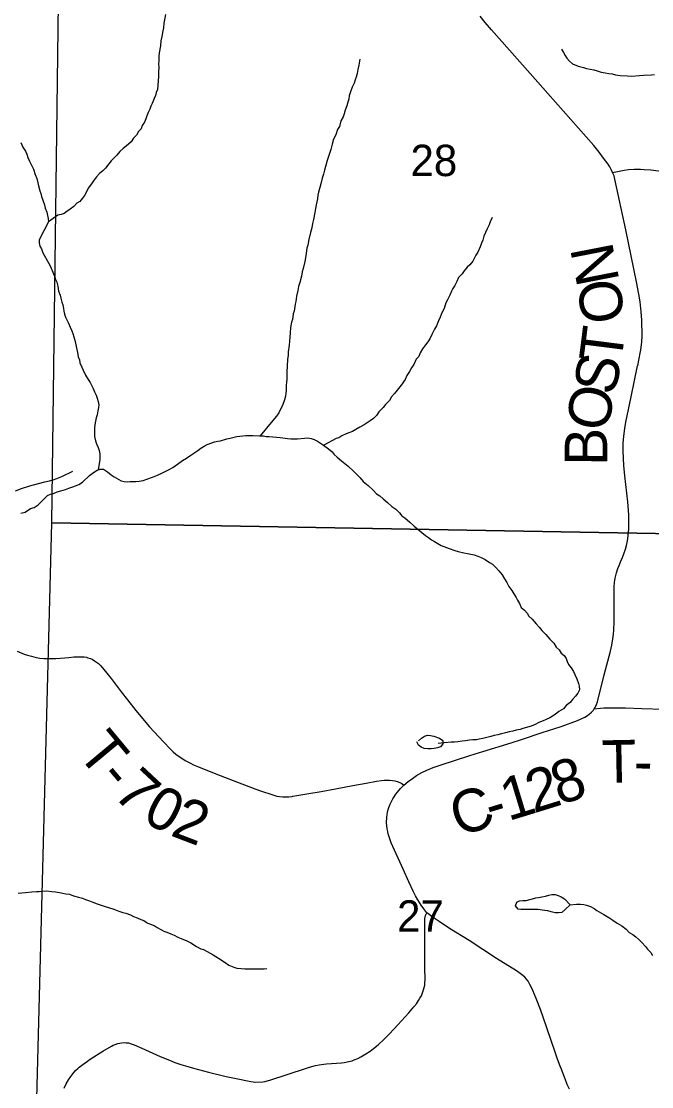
# Model space of a CAD drawing. Extents: x 0 to 34, y 0 to 22.
# Drawn here: x 27.832 to 28.673, y 16.803 to 18.224 of the extents above; entities that cross this region are included whole.
import ezdxf

# ---------------------------------------------------------------- set-up
doc = ezdxf.new("R2010")
doc.units = 0
for name, color, linetype in [('GM_X_Corporation', 7, 'Continuous'), ('GM_X_County_Road', 7, 'Continuous'), ('GM_X_County_Road_Text', 7, 'Continuous'), ('GM_X_Minor_River', 7, 'Continuous'), ('GM_X_Section_Text', 7, 'Continuous'), ('GM_X_Township_Road', 7, 'Continuous'), ('GM_X_Township_Road_Text', 7, 'Continuous')]:
    doc.layers.add(name, color=color, linetype=linetype)

msp = doc.modelspace()

# ---------------------------------------------------------------- linework, layer by layer
at = {"layer": 'GM_X_Corporation'}
for points in [[(28.8973, 18.5532), (28.8799, 17.5369), (27.873, 17.5549), (27.8861, 18.5601)], [(27.873, 17.5549), (28.8799, 17.5369), (28.863, 16.5324), (27.8467, 16.5483)]]:
    msp.add_lwpolyline(points, close=True, dxfattribs=at)
at = {"layer": 'GM_X_County_Road'}
for points in [[(28.6212, 18.0221), (28.6193, 18.0261), (28.6174, 18.0296), (28.6151, 18.0333), (28.6091, 18.0412), (28.6035, 18.0489), (28.596, 18.0578), (28.535, 18.1273), (28.5216, 18.1425), (28.4597, 18.2123), (28.4513, 18.222), (28.4445, 18.2303)], [(28.5637, 16.7997), (28.5607, 16.8061), (28.5582, 16.812), (28.5524, 16.8271), (28.5511, 16.8305), (28.5489, 16.8364), (28.5473, 16.8413), (28.5446, 16.8493), (28.5285, 16.8956), (28.5248, 16.9058), (28.5192, 16.9207), (28.5148, 16.9314), (28.5126, 16.9361), (28.511, 16.9392), (28.5085, 16.9436), (28.5062, 16.9466), (28.5039, 16.9492), (28.5013, 16.9515), (28.4979, 16.9542), (28.4928, 16.9577), (28.4662, 16.9742), (28.4299, 16.9978), (28.4038, 17.0138), (28.3897, 17.0231), (28.3806, 17.0295), (28.3763, 17.0328), (28.3735, 17.035), (28.3693, 17.0403), (28.366, 17.0449), (28.3612, 17.052), (28.3582, 17.0576), (28.355, 17.0639), (28.3495, 17.076), (28.3417, 17.0931), (28.326, 17.1282), (28.3235, 17.135), (28.322, 17.14), (28.3212, 17.1434), (28.3206, 17.1467), (28.32, 17.151), (28.3197, 17.1548), (28.3199, 17.1625), (28.3203, 17.1659), (28.3208, 17.1687), (28.3218, 17.1725), (28.3227, 17.1755), (28.3244, 17.1798), (28.3265, 17.184), (28.328, 17.1868), (28.3297, 17.1895), (28.3322, 17.1932), (28.3343, 17.1959), (28.3383, 17.2008), (28.3425, 17.2052), (28.3486, 17.2102), (28.3542, 17.2141), (28.3596, 17.2178), (28.3665, 17.2218), (28.3734, 17.2251), (28.3819, 17.2285), (28.3911, 17.2316), (28.4308, 17.2445), (28.4479, 17.2498), (28.4859, 17.2615), (28.4995, 17.2659), (28.5272, 17.2751), (28.5524, 17.2835), (28.5743, 17.2912), (28.5794, 17.2935), (28.5841, 17.2959), (28.5875, 17.2979), (28.5901, 17.2998), (28.5931, 17.3023), (28.5956, 17.3051), (28.5968, 17.3067), (28.598, 17.3087), (28.5999, 17.3128), (28.6012, 17.3163), (28.61, 17.3524), (28.6183, 17.3837), (28.6201, 17.3918), (28.6214, 17.4001), (28.6222, 17.4063), (28.6227, 17.4117), (28.6232, 17.4235), (28.6235, 17.4404), (28.6233, 17.4655), (28.6234, 17.4693), (28.6239, 17.4752), (28.6248, 17.4811), (28.6256, 17.4847), (28.6265, 17.4884), (28.6283, 17.4941), (28.6298, 17.4981), (28.6324, 17.5039), (28.6343, 17.5085), (28.6361, 17.5135), (28.6383, 17.5196), (28.6397, 17.5246), (28.6406, 17.5288), (28.6414, 17.5336), (28.6421, 17.5386), (28.6428, 17.5466), (28.643, 17.5529), (28.6428, 17.5654), (28.6414, 17.5827), (28.6376, 17.6176), (28.6362, 17.6314), (28.6356, 17.6407), (28.6353, 17.6509), (28.6355, 17.6609), (28.6358, 17.6658), (28.6366, 17.6739), (28.6375, 17.6807), (28.6389, 17.6891), (28.6459, 17.7231), (28.6546, 17.764), (28.6547, 17.7646), (28.6566, 17.774), (28.658, 17.7813), (28.6587, 17.7855), (28.66, 17.7959), (28.6606, 17.8042), (28.6603, 17.8249), (28.6595, 17.8362), (28.6579, 17.8494), (28.6563, 17.8599), (28.653, 17.8761), (28.6387, 17.9456), (28.6244, 18.0129), (28.6231, 18.0176), (28.6212, 18.0221)], [(28.6212, 18.0221), (28.6368, 18.0251), (28.6424, 18.0258), (28.65, 18.0263), (28.6586, 18.0264), (28.6633, 18.0262), (28.672, 18.0255), (28.6963, 18.0226)]]:
    msp.add_lwpolyline(points, dxfattribs=at)
at = {"layer": 'GM_X_Minor_River'}
for points in [[(28.0247, 18.2327), (28.0227, 18.2213), (28.022, 18.2148), (28.021, 18.211), (28.02, 18.2034), (28.0185, 18.1977), (28.0179, 18.1909), (28.0162, 18.1814), (28.0159, 18.1768), (28.016, 18.1707), (28.0153, 18.1666), (28.0157, 18.1628), (28.0155, 18.1552), (28.0152, 18.1502), (28.0147, 18.1385), (28.014, 18.1328), (28.0122, 18.1286), (28.0115, 18.1248), (28.0097, 18.1206), (28.0071, 18.1141), (28.0053, 18.1103), (28.0039, 18.1064), (28.0017, 18.1022), (27.9999, 18.0976), (27.9984, 18.0934), (27.9966, 18.0892), (27.9937, 18.0846), (27.9922, 18.0804), (27.9889, 18.0766), (27.9859, 18.0716), (27.9822, 18.0677), (27.9789, 18.0631), (27.9722, 18.057), (27.9681, 18.0538), (27.9636, 18.05), (27.9599, 18.045), (27.9521, 18.0376), (27.9491, 18.0334), (27.9447, 18.0276), (27.941, 18.0242), (27.9365, 18.0207), (27.9328, 18.0161), (27.9287, 18.0107), (27.9258, 18.0068), (27.9217, 18.0011), (27.9199, 17.9969), (27.9166, 17.9915), (27.914, 17.9877), (27.9103, 17.9834), (27.9065, 17.9811), (27.9025, 17.9768), (27.8976, 17.973), (27.8931, 17.9702), (27.8894, 17.9675), (27.8856, 17.9659), (27.8811, 17.9651), (27.8688, 17.9561), (27.8563, 17.9324), (27.8564, 17.9282), (27.8572, 17.9237), (27.8592, 17.92), (27.8612, 17.9151), (27.8686, 17.9015), (27.8713, 17.8967), (27.8753, 17.8869), (27.8772, 17.8831), (27.878, 17.8793), (27.8796, 17.8756), (27.8809, 17.8703), (27.8821, 17.8639), (27.8841, 17.8586)], [(28.553, 18.1864), (28.5557, 18.1819), (28.5577, 18.1781), (28.56, 18.1743), (28.5635, 18.1706), (28.5677, 18.1669), (28.5753, 18.164), (28.5826, 18.1619), (28.5864, 18.1608), (28.5963, 18.1587), (28.6008, 18.1576), (28.6061, 18.1558), (28.6115, 18.1548), (28.616, 18.1541), (28.6206, 18.1534), (28.6251, 18.1524), (28.6312, 18.1513), (28.641, 18.1508), (28.6467, 18.1505), (28.6569, 18.1514), (28.6626, 18.1519), (28.6732, 18.1521), (28.6773, 18.1525)], [(28.2838, 18.1732), (28.2825, 18.1649), (28.2814, 18.1595), (28.2804, 18.1538), (28.279, 18.1492), (28.2779, 18.1454), (28.2765, 18.1412), (28.2739, 18.1359), (28.2717, 18.1294), (28.2699, 18.1244), (28.2693, 18.1199), (28.2678, 18.1157), (28.2668, 18.1111), (28.2646, 18.105), (28.2632, 18.1004), (28.2617, 18.0962), (28.2588, 18.0909), (28.2567, 18.0832), (28.2541, 18.0794), (28.2519, 18.0722), (28.249, 18.0664), (28.2472, 18.0599), (28.2455, 18.0527), (28.2404, 18.0382), (28.2383, 18.0302), (28.2369, 18.0252), (28.2354, 18.0199), (28.2336, 18.0146), (28.2322, 18.0085), (28.2305, 18.002), (28.2287, 17.9959), (28.228, 17.9917), (28.2273, 17.9868), (28.2259, 17.9788), (28.2249, 17.9738), (28.2238, 17.9685), (28.2221, 17.9594), (28.2207, 17.954), (28.22, 17.9483), (28.2183, 17.9419), (28.2161, 17.9327), (28.2148, 17.9251), (28.2133, 17.9209), (28.212, 17.911), (28.2106, 17.9034), (28.2085, 17.8939), (28.2071, 17.8897), (28.206, 17.8836), (28.2039, 17.8752), (28.2021, 17.8699), (28.2011, 17.8646), (28.1993, 17.857), (28.1987, 17.8501), (28.1976, 17.8463), (28.1962, 17.8372), (28.1952, 17.8334), (28.1942, 17.8262), (28.1927, 17.8223), (28.1917, 17.8155), (28.1911, 17.8083), (28.1904, 17.8026), (28.1895, 17.7916), (28.1885, 17.7828), (28.1882, 17.7783), (28.1875, 17.7726), (28.1869, 17.7638), (28.1867, 17.7563), (28.1864, 17.7513), (28.1865, 17.7464), (28.1862, 17.7426), (28.1859, 17.738), (28.1856, 17.7324), (28.1853, 17.7274), (28.1846, 17.7236), (28.1835, 17.719), (28.1807, 17.7114), (28.1781, 17.7064), (28.1759, 17.7015), (28.173, 17.6969), (28.1659, 17.6888), (28.1511, 17.6707)], [(27.8317, 18.062), (27.8345, 18.0556)], [(27.8345, 18.0556), (27.838, 18.0504), (27.8396, 18.0466), (27.8412, 18.0421), (27.8435, 18.0372), (27.8455, 18.0327), (27.8486, 18.0263), (27.851, 18.0192), (27.853, 18.0139), (27.8542, 18.0082), (27.8554, 18.0041), (27.8571, 17.9977), (27.8586, 17.9939), (27.8591, 17.9901), (27.8631, 17.9788), (27.8643, 17.9746), (27.8663, 17.969), (27.8675, 17.9645), (27.8683, 17.9607), (27.8688, 17.9561)], [(28.4604, 17.9621), (28.4579, 17.956), (28.4565, 17.9522), (28.4539, 17.9468), (28.4495, 17.9369), (28.4481, 17.9319), (28.4463, 17.9277), (28.4445, 17.9228), (28.4412, 17.9159), (28.4386, 17.9117), (28.4346, 17.9036), (28.4309, 17.899), (28.4272, 17.8959), (28.4231, 17.8909), (28.4205, 17.8871), (28.4157, 17.882), (28.4135, 17.8767), (28.4106, 17.8713), (28.408, 17.8675), (28.4062, 17.8637), (28.404, 17.8583), (28.4011, 17.8522), (28.3989, 17.848), (28.3963, 17.8407), (28.3934, 17.835), (28.3912, 17.8293), (28.3891, 17.8243), (28.3862, 17.8174), (28.3836, 17.8132), (28.3803, 17.8067), (28.3774, 17.8002), (28.3748, 17.7964), (28.3718, 17.7922), (28.3678, 17.7868), (28.3645, 17.7814), (28.3627, 17.7768), (28.3593, 17.773), (28.356, 17.7661), (28.3531, 17.7615), (28.3501, 17.7565), (28.3468, 17.7515), (28.3443, 17.7462), (28.3391, 17.7385), (28.3354, 17.7342), (28.3302, 17.7273), (28.3261, 17.7227), (28.3236, 17.7181), (28.3184, 17.7127), (28.315, 17.7085), (28.3095, 17.7027), (28.3061, 17.6981), (28.3024, 17.6939), (28.2976, 17.6907), (28.2938, 17.6884), (28.2897, 17.6857), (28.2841, 17.6825), (28.2788, 17.6794), (28.274, 17.6767), (28.2695, 17.6747), (28.2657, 17.6735), (28.2601, 17.6711), (28.2559, 17.6684), (28.2522, 17.6672), (28.236, 17.6583)], [(27.8841, 17.8586), (27.8849, 17.8544), (27.8865, 17.8491), (27.8877, 17.8454), (27.8886, 17.8408), (27.889, 17.8371), (27.8898, 17.8329), (27.8914, 17.8291), (27.8953, 17.8209), (27.8977, 17.8156), (27.8997, 17.8111), (27.9013, 17.8073), (27.9025, 17.8028), (27.9041, 17.7968), (27.9057, 17.79), (27.9065, 17.7862), (27.9074, 17.782), (27.9082, 17.7764), (27.9098, 17.7722), (27.9106, 17.7684), (27.913, 17.7624), (27.915, 17.7583), (27.9181, 17.7519), (27.9216, 17.7459), (27.924, 17.7421), (27.9259, 17.7384), (27.9283, 17.7342), (27.9302, 17.7297), (27.9322, 17.7252), (27.9334, 17.7211), (27.935, 17.7165), (27.9358, 17.7124), (27.9355, 17.7086), (27.9344, 17.7044), (27.9334, 17.6991), (27.9323, 17.6949), (27.9313, 17.6903), (27.9306, 17.6854), (27.9299, 17.6816), (27.9301, 17.6698), (27.9314, 17.6642), (27.9326, 17.6604), (27.9349, 17.6555), (27.9361, 17.6513), (27.937, 17.6468), (27.9371, 17.6392), (27.9347, 17.6255)], [(27.9472, 17.6231), (27.9522, 17.619), (27.9564, 17.6161), (27.9656, 17.6109), (27.9698, 17.6099), (27.9739, 17.6095), (27.9777, 17.61), (27.9853, 17.6101), (27.9894, 17.6106), (27.9951, 17.6114), (28, 17.613), (28.0075, 17.6158), (28.0139, 17.6186), (28.0207, 17.6214), (28.0297, 17.6261), (28.0345, 17.6288), (28.0409, 17.6331), (28.0476, 17.6378), (28.0528, 17.6413), (28.0585, 17.6452), (28.0678, 17.6514), (28.0719, 17.6545), (28.0764, 17.6569), (28.0805, 17.6592), (28.0865, 17.6616), (28.0903, 17.6628), (28.0945, 17.6636), (28.0982, 17.6644), (28.1065, 17.6669), (28.111, 17.6677), (28.1163, 17.6693), (28.1201, 17.6698), (28.128, 17.671), (28.1318, 17.6715), (28.1371, 17.6712), (28.1412, 17.6713), (28.15, 17.6707), (28.1553, 17.6708), (28.159, 17.6701), (28.1632, 17.6698), (28.1727, 17.6692), (28.1776, 17.6685), (28.1814, 17.6682), (28.1875, 17.6675), (28.192, 17.6669), (28.2007, 17.667), (28.2102, 17.6679), (28.2147, 17.668), (28.2189, 17.6673), (28.2231, 17.6659), (28.2273, 17.6637), (28.2357, 17.6585), (28.2422, 17.6537), (28.2472, 17.6496), (28.2499, 17.6459), (28.2537, 17.6426), (28.2595, 17.6377), (28.2641, 17.634), (28.2683, 17.6303), (28.2753, 17.624), (28.2845, 17.615), (28.2884, 17.6098), (28.2949, 17.6046), (28.3018, 17.5983), (28.3061, 17.5934), (28.3106, 17.5909), (28.3149, 17.5871), (28.321, 17.5819), (28.3268, 17.5767), (28.3318, 17.573), (28.3371, 17.5682), (28.3399, 17.5641), (28.3441, 17.5615), (28.3506, 17.5559), (28.3564, 17.5503), (28.3667, 17.5422), (28.3717, 17.5381), (28.3756, 17.5355), (28.3794, 17.5322), (28.3836, 17.53), (28.3882, 17.5274), (28.3924, 17.5248), (28.3962, 17.5234), (28.4031, 17.5208), (28.4107, 17.5179), (28.4152, 17.5165), (28.4228, 17.5151), (28.4278, 17.5141), (28.4319, 17.513), (28.4365, 17.5123), (28.4414, 17.5105), (28.446, 17.5087), (28.451, 17.5058), (28.4571, 17.5021), (28.4609, 17.4999), (28.4656, 17.4954), (28.4694, 17.4909), (28.4737, 17.4857), (28.4768, 17.4804), (28.4803, 17.4752), (28.4826, 17.4699)], [(27.8316, 17.5676), (27.8373, 17.5692), (27.8448, 17.5739), (27.8497, 17.5755), (27.8549, 17.579), (27.859, 17.5829), (27.8635, 17.5875), (27.8675, 17.5914), (27.8713, 17.5929), (27.8751, 17.5942), (27.8803, 17.5961), (27.8852, 17.5974), (27.8912, 17.5994), (27.8958, 17.601), (27.901, 17.603), (27.9048, 17.6042), (27.9093, 17.6061), (27.9138, 17.6092), (27.9235, 17.6178), (27.9287, 17.622), (27.9336, 17.6251), (27.9377, 17.6263), (27.9422, 17.6264), (27.9472, 17.6231)], [(28.4826, 17.4699), (28.4869, 17.4647), (28.4896, 17.4602), (28.4927, 17.4553), (28.4943, 17.4516), (28.497, 17.4474), (28.4994, 17.4422), (28.5036, 17.4385), (28.5071, 17.4343), (28.5094, 17.4306), (28.5137, 17.4265), (28.5191, 17.4202), (28.5233, 17.4157), (28.5268, 17.4112), (28.5322, 17.406), (28.5376, 17.3996), (28.543, 17.3944), (28.5461, 17.3892), (28.5499, 17.3854), (28.5527, 17.3809), (28.5565, 17.378), (28.5592, 17.3739), (28.5608, 17.3701), (28.5624, 17.3659), (28.5659, 17.3615), (28.569, 17.3566), (28.5706, 17.3528), (28.5733, 17.3468), (28.5757, 17.3408), (28.5765, 17.337), (28.577, 17.3321), (28.5748, 17.3279), (28.5718, 17.3237), (28.5677, 17.3194), (28.5644, 17.3152), (28.5592, 17.3113), (28.5555, 17.3067), (28.5495, 17.3032), (28.5446, 17.2993), (28.5375, 17.295), (28.5326, 17.2926), (28.5285, 17.291), (28.5229, 17.2887), (28.518, 17.2859), (28.5124, 17.2839), (28.5014, 17.2807), (28.4977, 17.2795), (28.4924, 17.2786), (28.4883, 17.2771), (28.483, 17.2762), (28.4781, 17.275), (28.4732, 17.2734), (28.4683, 17.2721), (28.4634, 17.2713), (28.4589, 17.2701), (28.4532, 17.2688), (28.4483, 17.2672), (28.4434, 17.2664), (28.4397, 17.2656), (28.4347, 17.2655), (28.4302, 17.265), (28.4249, 17.2642), (28.4204, 17.2637), (28.4147, 17.2629), (28.4102, 17.2624), (28.4057, 17.2623), (28.3966, 17.2614), (28.3887, 17.2605)], [(28.3621, 17.2642), (28.3662, 17.2677), (28.3703, 17.2704), (28.3741, 17.2716), (28.3783, 17.2713), (28.3828, 17.2706), (28.3904, 17.2677), (28.3946, 17.2648), (28.3947, 17.2602), (28.3914, 17.2564), (28.3876, 17.2548), (28.3831, 17.254), (28.3793, 17.2535), (28.3748, 17.2534), (28.3699, 17.2541), (28.366, 17.2556), (28.3622, 17.2585), (28.3602, 17.2627)], [(27.8283, 17.0611), (27.8378, 17.062), (27.8465, 17.0629), (27.8525, 17.0634), (27.8563, 17.0634), (27.8608, 17.0639), (27.8665, 17.064), (27.8733, 17.0634)], [(27.8733, 17.0634), (27.8779, 17.0627), (27.8832, 17.062), (27.8877, 17.0613), (27.8919, 17.0603), (27.8968, 17.0596), (27.9022, 17.0574), (27.9086, 17.0556), (27.914, 17.0546), (27.9181, 17.0528), (27.9235, 17.051), (27.928, 17.0492), (27.9334, 17.047), (27.9391, 17.0452), (27.9444, 17.0434), (27.9486, 17.0419), (27.9558, 17.0398), (27.9623, 17.0373), (27.968, 17.0355), (27.9718, 17.0344), (27.9779, 17.0322), (27.9821, 17.03), (27.9871, 17.0282), (27.9916, 17.026), (27.9958, 17.0246), (28.0004, 17.0216), (28.0058, 17.0191), (28.0096, 17.018), (28.0134, 17.0154), (28.0187, 17.0125), (28.0226, 17.0103), (28.0267, 17.0092), (28.0317, 17.007), (28.0363, 17.0052), (28.0412, 17.0026), (28.0458, 17.0008), (28.0531, 16.9975), (28.0584, 16.995), (28.0661, 16.9898), (28.0718, 16.9869), (28.0756, 16.9858), (28.0802, 16.9832), (28.0882, 16.9788), (28.0955, 16.9744), (28.1043, 16.9685), (28.1092, 16.9652), (28.1161, 16.9623), (28.1199, 16.9612), (28.1256, 16.9605), (28.1305, 16.9602), (28.1343, 16.9603), (28.1381, 16.96), (28.1562, 16.9603), (28.16, 16.9608)], [(28.5647, 17.0454), (28.5579, 17.0394), (28.5534, 17.0352), (28.5492, 17.0347), (28.5447, 17.035), (28.5394, 17.0361), (28.5348, 17.0375), (28.531, 17.0382), (28.5272, 17.0385), (28.5219, 17.0392), (28.5177, 17.0391), (28.5128, 17.0394), (28.5037, 17.0392), (28.4988, 17.0395), (28.495, 17.0398), (28.4916, 17.044), (28.4934, 17.0489), (28.4971, 17.0509), (28.5016, 17.0513), (28.5058, 17.0514), (28.5107, 17.0526), (28.5145, 17.0535), (28.5186, 17.0547), (28.5224, 17.0551), (28.5269, 17.056), (28.5318, 17.0572), (28.5363, 17.0584), (28.5401, 17.0592), (28.5446, 17.0593), (28.5484, 17.0582), (28.5526, 17.056), (28.5572, 17.0535), (28.5647, 17.0454)], [(28.5647, 17.0454), (28.5732, 17.0465), (28.5785, 17.0466), (28.5827, 17.0459), (28.5865, 17.0453), (28.5918, 17.0431), (28.5964, 17.0405), (28.6003, 17.0379), (28.6094, 17.0328), (28.6163, 17.0287), (28.6217, 17.025), (28.6274, 17.0213), (28.6335, 17.0177), (28.6393, 17.0132), (28.6431, 17.0087), (28.6481, 17.0058), (28.652, 17.0028), (28.6562, 16.9991), (28.66, 16.9954), (28.665, 16.9902), (28.6677, 16.9864), (28.672, 16.9819), (28.6743, 16.9782)]]:
    msp.add_lwpolyline(points, dxfattribs=at)
at = {"layer": 'GM_X_Township_Road'}
for points in [[(27.8244, 17.5976), (27.8324, 17.6007), (27.8436, 17.6044), (27.8551, 17.6075), (27.8639, 17.6096), (27.8698, 17.6108), (27.8747, 17.6121), (27.8799, 17.614), (27.8863, 17.6167), (27.9013, 17.6236)], [(27.827, 17.3837), (27.8362, 17.3799), (27.8405, 17.3785), (27.8458, 17.3769), (27.8524, 17.3754), (27.8572, 17.3745), (27.8624, 17.3739), (27.8671, 17.3738), (27.8784, 17.374), (27.8846, 17.3744), (27.8906, 17.3749), (27.8959, 17.3754), (27.9026, 17.3761), (27.9074, 17.3763), (27.9128, 17.3763), (27.916, 17.3761), (27.9193, 17.3756), (27.9213, 17.3749), (27.9247, 17.3738), (27.9267, 17.3729), (27.9302, 17.3708), (27.9327, 17.3691), (27.9352, 17.3671), (27.9386, 17.3641), (27.9466, 17.3545), (27.9524, 17.3471), (27.9658, 17.3296), (27.974, 17.3187), (27.9851, 17.3047), (28.0034, 17.283), (28.0094, 17.2763), (28.0219, 17.2629), (28.0313, 17.253), (28.035, 17.2496), (28.0387, 17.2466), (28.0416, 17.2443), (28.0463, 17.241), (28.0508, 17.238), (28.0571, 17.2347), (28.0623, 17.2323), (28.0686, 17.2296), (28.0743, 17.2272), (28.0977, 17.2181), (28.1206, 17.2091), (28.1451, 17.1998), (28.1514, 17.1974), (28.1678, 17.1921), (28.1731, 17.1906), (28.1768, 17.19), (28.1814, 17.1896), (28.1857, 17.1895), (28.1892, 17.1897), (28.1935, 17.1902), (28.1945, 17.1904)], [(28.5968, 17.3067), (28.6049, 17.3076), (28.6094, 17.308), (28.6147, 17.3083), (28.6179, 17.3083), (28.6382, 17.3082), (28.6601, 17.3074), (28.689, 17.3065)], [(28.1945, 17.1904), (28.2134, 17.1935), (28.2324, 17.1965), (28.2517, 17.2002), (28.2746, 17.2046), (28.2923, 17.2079), (28.3063, 17.2104), (28.3131, 17.2115), (28.3163, 17.2117), (28.3196, 17.2118), (28.3237, 17.2117), (28.3275, 17.2114), (28.3305, 17.2109), (28.3339, 17.21), (28.3373, 17.2086), (28.3398, 17.2071), (28.3425, 17.2052)], [(27.8894, 16.8012), (27.892, 16.8068), (27.8951, 16.812), (27.8983, 16.8167), (27.9009, 16.82), (27.9048, 16.8245), (27.9076, 16.8271), (27.9097, 16.8291), (27.9256, 16.8405), (27.9409, 16.8502), (27.9528, 16.8572), (27.9547, 16.8583), (27.9574, 16.8595), (27.9612, 16.8608), (27.9637, 16.8613), (27.9662, 16.8617), (27.9704, 16.8619), (27.9724, 16.8617), (27.9752, 16.8614), (27.9791, 16.8604), (27.9828, 16.8589), (27.993, 16.8544), (28.003, 16.8498), (28.0178, 16.8432), (28.03, 16.8382), (28.0371, 16.8355), (28.0454, 16.8327), (28.0516, 16.8307), (28.062, 16.8277), (28.082, 16.8225), (28.1055, 16.8168), (28.1188, 16.8141), (28.1386, 16.8099), (28.1448, 16.8093), (28.1544, 16.8096), (28.1571, 16.81), (28.1622, 16.8112), (28.1638, 16.8116), (28.2114, 16.8271), (28.217, 16.8291), (28.2247, 16.8312), (28.2297, 16.8322), (28.2361, 16.8332), (28.2394, 16.8335), (28.2595, 16.8349), (28.2632, 16.8353), (28.2694, 16.8365), (28.2736, 16.8376), (28.2766, 16.8387), (28.2811, 16.8405), (28.2855, 16.8427), (28.2921, 16.8467), (28.2977, 16.8506), (28.3022, 16.8539), (28.3086, 16.859), (28.316, 16.8661), (28.3234, 16.8737), (28.3346, 16.8855), (28.3493, 16.9017), (28.3562, 16.9095), (28.3594, 16.9137), (28.3624, 16.918), (28.3642, 16.9211), (28.3661, 16.9244), (28.3678, 16.9282), (28.369, 16.9323), (28.3698, 16.9352), (28.3705, 16.9386), (28.3709, 16.9419), (28.371, 16.9451), (28.3709, 16.9625), (28.3706, 16.9759), (28.3709, 17.0275), (28.3718, 17.0311), (28.3735, 17.035)]]:
    msp.add_lwpolyline(points, dxfattribs=at)

# ---------------------------------------------------------------- texts
at = {"layer": 'GM_X_County_Road_Text'}
for s, rotation, p in [('N', 101.0152, (28.6305, 17.8777)), ('O', 97.7259, (28.6378, 17.8247)), ('T', 82.8184, (28.6326, 17.7664)), ('S', 77.4903, (28.6233, 17.7233)), ('O', 79.1637, (28.614, 17.6746)), ('B', 89.5355, (28.6139, 17.6307)), ('8', 18.3239, (28.5503, 17.1781)), ('1', 16.8925, (28.4819, 17.157)), ('2', 17.2927, (28.5158, 17.1673)), ('C', 18.0067, (28.4155, 17.1359)), ('-', 16.8907, (28.4596, 17.1502))]:
    msp.add_text(s, height=0.0568, rotation=rotation, dxfattribs=at).set_placement(p)
at = {"layer": 'GM_X_Section_Text'}
for s, p in [('28', (28.3516, 18.0172)), ('27', (28.3337, 17.0097))]:
    msp.add_text(s, height=0.04186, rotation=0, dxfattribs=at).set_placement(p)
at = {"layer": 'GM_X_Township_Road_Text'}
for s, rotation, p in [('T', 309.7167, (27.9054, 17.2476)), ('T', 1.1122, (28.6071, 17.208)), ('-', 359.0437, (28.649, 17.2088)), ('-', 310.1851, (27.9329, 17.2145)), ('7', 316.9869, (27.953, 17.1913)), ('0', 332.1522, (27.9919, 17.158)), ('2', 339.151, (28.0297, 17.1385))]:
    msp.add_text(s, height=0.0568, rotation=rotation, dxfattribs=at).set_placement(p)

doc.saveas('drawing.dxf')
